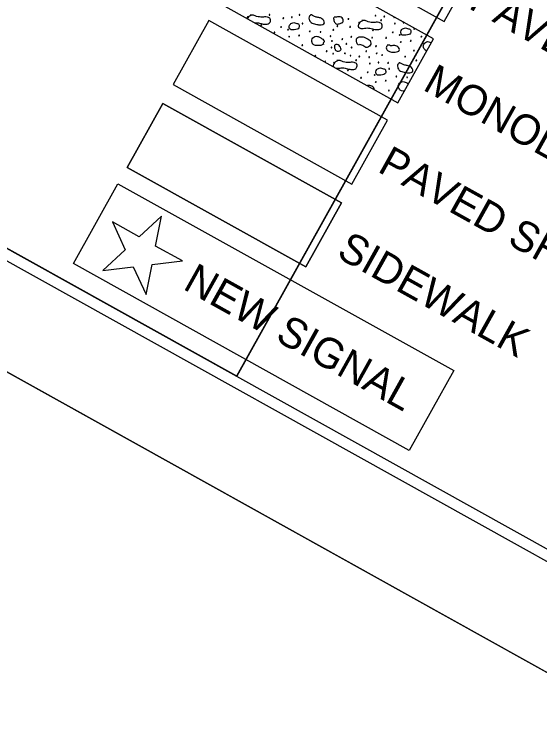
# Model space of a CAD drawing. Extents: x 1763454 to 1765483, y 710212 to 712009.
# Drawn here: x 1764801.1 to 1764922.7, y 710212.4 to 710377.6 of the extents above; entities that cross this region are included whole.
import ezdxf

# ---------------------------------------------------------------- set-up
doc = ezdxf.new("R2010")
doc.units = 0
for name, color, linetype in [('Default', 7, 'Continuous'), ('Matchline', 7, 'Continuous'), ('Old_Level_40', 7, 'Continuous'), ('Prop DSN Text', 7, 'Continuous'), ('Prop Grid Mask', 7, 'Continuous'), ('Prop RDY Traffic Signal CELL', 7, 'Continuous'), ('Prop Shade Light', 7, 'Continuous'), ('Prop Shade Medium', 7, 'Continuous'), ('Sheet Border Standard 30in CELL', 7, 'Continuous'), ('Sheet Cutting Line CELL', 7, 'Continuous'), ('Sheet Layout Plan Border', 7, 'Continuous'), ('Sheet Plot Border Inside CELL', 7, 'Continuous'), ('Sheet Plot Border Outside CELL', 7, 'Continuous')]:
    doc.layers.add(name, color=color, linetype=linetype)

msp = doc.modelspace()

# ---------------------------------------------------------------- linework, layer by layer
at = {"layer": 'Default'}
msp.add_lwpolyline([(1763634.19, 710972.32), (1763634.19, 710972.32), (1763806.94, 711282.53), (1764422.61, 711735.08), (1765280.77, 711257.19), (1765145.7, 711014.65), (1765228.38, 710968.6), (1764852.61, 710293.81)], close=True, dxfattribs=at)
at = {"layer": 'Matchline'}
for points in [[(1764854.98, 710376.93), (1764854.96, 710376.88), (1764855.1, 710376.82), (1764855.22, 710376.94), (1764855.12, 710377.03), (1764855.05, 710376.98), (1764855.01, 710376.94), (1764855, 710376.92)], [(1764855.86, 710377.31), (1764855.46, 710377.17), (1764855.16, 710376.91), (1764854.98, 710376.6)], [(1764856.67, 710375.67), (1764856.84, 710375.67), (1764857.67, 710375.67), (1764858.45, 710375.36), (1764859.47, 710375.3), (1764859.82, 710375.39), (1764860.37, 710375.63), (1764860.52, 710376.67), (1764859.71, 710377.02), (1764858.97, 710377.06), (1764858.56, 710376.89), (1764857.85, 710377.01), (1764857.23, 710377.05), (1764856.46, 710377.5), (1764855.96, 710377.44), (1764855.71, 710377.39)], [(1764860.07, 710377.5), (1764860.05, 710377.45), (1764860.19, 710377.39), (1764860.3, 710377.51), (1764860.21, 710377.6), (1764860.13, 710377.55), (1764860.1, 710377.52), (1764860.08, 710377.49)], [(1764863.26, 710376.72), (1764863.25, 710376.68), (1764863.38, 710376.62), (1764863.49, 710376.74), (1764863.4, 710376.82), (1764863.33, 710376.77), (1764863.29, 710376.74), (1764863.28, 710376.72)], [(1764865.25, 710376.95), (1764865.23, 710376.9), (1764865.37, 710376.83), (1764865.48, 710376.96), (1764865.39, 710377.04), (1764865.32, 710377), (1764865.28, 710376.96), (1764865.27, 710376.94)], [(1764867.03, 710377.49), (1764867.02, 710377.44), (1764867.15, 710377.38), (1764867.26, 710377.5), (1764867.17, 710377.58), (1764867.1, 710377.54), (1764867.06, 710377.5), (1764867.05, 710377.48)], [(1764869.7, 710377.36), (1764869.47, 710377.29), (1764869.28, 710377.04), (1764869.32, 710376.46), (1764869.66, 710375.64), (1764870.91, 710375.27), (1764871.76, 710375.17), (1764872.54, 710375.24), (1764873.02, 710375.59), (1764872.73, 710376.23), (1764872.36, 710376.62), (1764871.6, 710376.93), (1764870.74, 710376.91), (1764870.17, 710377.45), (1764869.74, 710377.52), (1764869.65, 710377.53)], [(1764875.03, 710376.96), (1764875, 710376.49), (1764875.12, 710375.96), (1764875.54, 710375.26), (1764876.3, 710375.42), (1764877.07, 710375.69), (1764877.28, 710375.87), (1764877.22, 710376.33), (1764877.03, 710376.81), (1764876.51, 710377.06), (1764876.08, 710377.03), (1764875.69, 710376.99), (1764875.3, 710376.96), (1764875.12, 710376.95)], [(1764884.6, 710377.3), (1764884.58, 710377.25), (1764884.72, 710377.19), (1764884.83, 710377.31), (1764884.74, 710377.39), (1764884.67, 710377.34), (1764884.63, 710377.31), (1764884.62, 710377.29)], [(1764886.65, 710377.09), (1764886.62, 710377.05), (1764886.76, 710376.98), (1764886.88, 710377.1), (1764886.78, 710377.19), (1764886.71, 710377.14), (1764886.68, 710377.11), (1764886.66, 710377.09)], [(1764888.92, 710376.96), (1764888.9, 710376.91), (1764889.04, 710376.85), (1764889.13, 710376.96), (1764889.13, 710376.98)], [(1764889.03, 710377.04), (1764889.02, 710377.03), (1764888.99, 710377), (1764888.96, 710376.97), (1764888.94, 710376.95)], [(1764858.19, 710375.16), (1764858.17, 710375.11), (1764858.31, 710375.04), (1764858.43, 710375.16), (1764858.33, 710375.25), (1764858.26, 710375.2), (1764858.22, 710375.17), (1764858.21, 710375.15)], [(1764865.8, 710375.73), (1764865.45, 710375.65), (1764864.9, 710375.4), (1764864.67, 710374.79), (1764864.81, 710374.27), (1764865.05, 710374), (1764865.92, 710374.02), (1764866.6, 710374.11), (1764867.09, 710374.46), (1764867.04, 710374.88), (1764867.02, 710375.31), (1764866.7, 710375.49), (1764866.29, 710375.53), (1764865.93, 710375.67), (1764865.8, 710375.73)], [(1764867.72, 710375.49), (1764867.7, 710375.44), (1764867.84, 710375.38), (1764867.95, 710375.5), (1764867.85, 710375.59), (1764867.78, 710375.54), (1764867.75, 710375.5), (1764867.73, 710375.48)], [(1764878.33, 710376.54), (1764878.31, 710376.49), (1764878.45, 710376.42), (1764878.56, 710376.55), (1764878.46, 710376.63), (1764878.39, 710376.59), (1764878.36, 710376.55), (1764878.34, 710376.53)], [(1764881.69, 710376.07), (1764881.27, 710375.92), (1764880.95, 710375.63), (1764880.7, 710375.13), (1764880.69, 710374.91), (1764880.89, 710374.39), (1764881.73, 710374.31), (1764883.18, 710374.56), (1764884.28, 710374.12), (1764885.3, 710374.06), (1764885.66, 710374.15), (1764886.21, 710374.39), (1764886.35, 710375.43), (1764885.54, 710375.78), (1764884.8, 710375.82), (1764884.4, 710375.65), (1764883.68, 710375.76), (1764883.06, 710375.81), (1764882.3, 710376.25), (1764881.79, 710376.2), (1764881.54, 710376.15)], [(1764880.81, 710375.69), (1764880.8, 710375.64), (1764880.93, 710375.58), (1764881.05, 710375.7), (1764880.95, 710375.78), (1764880.88, 710375.73), (1764880.85, 710375.7), (1764880.83, 710375.68)], [(1764885.9, 710376.26), (1764885.88, 710376.21), (1764886.02, 710376.15), (1764886.14, 710376.27), (1764886.04, 710376.35), (1764885.97, 710376.31), (1764885.93, 710376.27), (1764885.92, 710376.25)], [(1764889.1, 710375.48), (1764889.08, 710375.43), (1764889.22, 710375.37), (1764889.33, 710375.49), (1764889.23, 710375.57), (1764889.16, 710375.53), (1764889.13, 710375.49), (1764889.11, 710375.47)], [(1764891.08, 710375.7), (1764891.06, 710375.66), (1764891.21, 710375.59), (1764891.32, 710375.71), (1764891.22, 710375.8), (1764891.15, 710375.75), (1764891.12, 710375.72), (1764891.1, 710375.7)], [(1764861.22, 710373.42), (1764861.19, 710373.37), (1764861.34, 710373.31), (1764861.45, 710373.43), (1764861.35, 710373.52), (1764861.28, 710373.47), (1764861.24, 710373.43), (1764861.23, 710373.41)], [(1764862.76, 710374.7), (1764862.74, 710374.65), (1764862.87, 710374.59), (1764862.99, 710374.71), (1764862.89, 710374.79), (1764862.82, 710374.74), (1764862.79, 710374.71), (1764862.77, 710374.69)], [(1764864.36, 710374.05), (1764864.34, 710374), (1764864.48, 710373.94), (1764864.59, 710374.06), (1764864.49, 710374.15), (1764864.42, 710374.1), (1764864.39, 710374.06), (1764864.37, 710374.04)], [(1764869.38, 710373.69), (1764869.37, 710373.64), (1764869.5, 710373.58), (1764869.62, 710373.7), (1764869.52, 710373.78), (1764869.45, 710373.74), (1764869.41, 710373.7), (1764869.4, 710373.68)], [(1764871.88, 710373.53), (1764871.86, 710373.48), (1764872, 710373.41), (1764872.11, 710373.54), (1764872.01, 710373.62), (1764871.94, 710373.58), (1764871.91, 710373.54), (1764871.89, 710373.52)], [(1764874.84, 710374.02), (1764874.82, 710373.97), (1764874.96, 710373.91), (1764875.08, 710374.03), (1764874.97, 710374.12), (1764874.91, 710374.07), (1764874.87, 710374.04), (1764874.86, 710374.01)], [(1764875.78, 710374.88), (1764875.76, 710374.83), (1764875.9, 710374.77), (1764876.01, 710374.89), (1764875.91, 710374.98), (1764875.84, 710374.93), (1764875.81, 710374.89), (1764875.79, 710374.87)], [(1764878.72, 710374.72), (1764878.7, 710374.68), (1764878.84, 710374.61), (1764878.95, 710374.73), (1764878.85, 710374.82), (1764878.79, 710374.77), (1764878.75, 710374.74), (1764878.73, 710374.72)], [(1764884.03, 710373.91), (1764884.01, 710373.86), (1764884.14, 710373.8), (1764884.26, 710373.92), (1764884.16, 710374.01), (1764884.09, 710373.96), (1764884.06, 710373.93), (1764884.04, 710373.9)], [(1764888.59, 710373.45), (1764888.57, 710373.41), (1764888.71, 710373.34), (1764888.83, 710373.46), (1764888.73, 710373.55), (1764888.66, 710373.5), (1764888.62, 710373.47), (1764888.61, 710373.45)], [(1764891.63, 710374.49), (1764891.29, 710374.4), (1764890.73, 710374.16), (1764890.5, 710373.54), (1764890.65, 710373.02), (1764890.88, 710372.76), (1764891.76, 710372.78), (1764892.44, 710372.87), (1764892.93, 710373.21), (1764892.87, 710373.63), (1764892.85, 710374.06), (1764892.54, 710374.25), (1764892.13, 710374.29), (1764891.76, 710374.43), (1764891.63, 710374.49)], [(1764893.55, 710374.25), (1764893.53, 710374.2), (1764893.67, 710374.13), (1764893.79, 710374.26), (1764893.69, 710374.34), (1764893.62, 710374.3), (1764893.58, 710374.26), (1764893.57, 710374.24)], [(1764864.62, 710372.46), (1764864.6, 710372.41), (1764864.74, 710372.35), (1764864.85, 710372.47), (1764864.75, 710372.55), (1764864.68, 710372.51), (1764864.65, 710372.47), (1764864.63, 710372.45)], [(1764866.92, 710372.72), (1764866.9, 710372.68), (1764867.03, 710372.61), (1764867.15, 710372.73), (1764867.05, 710372.82), (1764866.98, 710372.77), (1764866.95, 710372.74), (1764866.93, 710372.72)], [(1764872.76, 710370.69), (1764872.19, 710370.4), (1764871.53, 710370.33), (1764870.52, 710370.39), (1764870.04, 710370.85), (1764869.85, 710371.74), (1764870.21, 710372.16), (1764870.61, 710372.51), (1764871.31, 710372.56), (1764871.89, 710372.27), (1764872.57, 710371.81), (1764872.84, 710371.46), (1764872.88, 710371.17), (1764872.66, 710371.13), (1764872.63, 710370.94), (1764872.62, 710370.88), (1764872.63, 710370.81)], [(1764874.19, 710372.57), (1764874.17, 710372.52), (1764874.31, 710372.45), (1764874.42, 710372.58), (1764874.32, 710372.66), (1764874.25, 710372.62), (1764874.22, 710372.58), (1764874.2, 710372.56)], [(1764876.92, 710371.87), (1764876.9, 710371.83), (1764877.04, 710371.76), (1764877.16, 710371.89), (1764877.06, 710371.97), (1764876.99, 710371.92), (1764876.95, 710371.89), (1764876.94, 710371.87)], [(1764879.01, 710372.41), (1764878.99, 710372.36), (1764879.12, 710372.3), (1764879.24, 710372.42), (1764879.14, 710372.51), (1764879.07, 710372.46), (1764879.04, 710372.43), (1764879.02, 710372.4)], [(1764880.89, 710370.58), (1764880.65, 710370.36), (1764880.35, 710371.04), (1764880.28, 710371.71), (1764880.32, 710372.13), (1764880.91, 710372.39), (1764881.73, 710372.49), (1764882.4, 710372.18), (1764883.08, 710371.8), (1764883.47, 710371.68), (1764883.72, 710370.85), (1764883.49, 710370.47), (1764883.21, 710370), (1764882.37, 710369.87), (1764882.1, 710370.31), (1764881.47, 710370.51), (1764881.27, 710370.58), (1764881.06, 710370.64)], [(1764883.85, 710372.19), (1764883.83, 710372.15), (1764883.97, 710372.08), (1764884.08, 710372.21), (1764883.99, 710372.29), (1764883.91, 710372.24), (1764883.88, 710372.21), (1764883.86, 710372.19)], [(1764887.05, 710372.18), (1764887.03, 710372.13), (1764887.17, 710372.06), (1764887.28, 710372.19), (1764887.18, 710372.27), (1764887.11, 710372.22), (1764887.08, 710372.19), (1764887.06, 710372.17)], [(1764890.19, 710372.81), (1764890.17, 710372.76), (1764890.31, 710372.69), (1764890.42, 710372.82), (1764890.33, 710372.9), (1764890.26, 710372.86), (1764890.22, 710372.82), (1764890.21, 710372.8)], [(1764895.22, 710372.44), (1764895.2, 710372.4), (1764895.34, 710372.33), (1764895.45, 710372.46), (1764895.35, 710372.54), (1764895.28, 710372.49), (1764895.25, 710372.46), (1764895.23, 710372.44)], [(1764867.66, 710370.45), (1764867.64, 710370.4), (1764867.78, 710370.33), (1764867.9, 710370.46), (1764867.8, 710370.54), (1764867.73, 710370.5), (1764867.69, 710370.46), (1764867.68, 710370.44)], [(1764874.52, 710371.44), (1764874.5, 710371.39), (1764874.64, 710371.33), (1764874.75, 710371.45), (1764874.66, 710371.53), (1764874.59, 710371.49), (1764874.55, 710371.45), (1764874.53, 710371.43)], [(1764875.4, 710369.62), (1764875.29, 710369.31), (1764875.94, 710368.97), (1764876.43, 710369.09), (1764876.84, 710369.46), (1764876.62, 710369.99), (1764876.35, 710370.42), (1764875.83, 710370.71), (1764875.27, 710370.61), (1764875.15, 710370.25), (1764875.21, 710369.9), (1764875.24, 710369.79), (1764875.29, 710369.68)], [(1764877.86, 710370.77), (1764877.84, 710370.72), (1764877.97, 710370.66), (1764878.09, 710370.78), (1764877.99, 710370.86), (1764877.92, 710370.82), (1764877.89, 710370.78), (1764877.87, 710370.76)], [(1764884.72, 710370.26), (1764884.7, 710370.21), (1764884.84, 710370.14), (1764884.95, 710370.26), (1764884.86, 710370.35), (1764884.79, 710370.3), (1764884.75, 710370.27), (1764884.74, 710370.25)], [(1764887.33, 710370.34), (1764887.26, 710370.12), (1764887.13, 710369.95), (1764887.3, 710369.28), (1764887.88, 710368.95), (1764888.91, 710368.8), (1764889.57, 710368.89), (1764890.13, 710369.06), (1764890.33, 710369.44), (1764890.09, 710369.95), (1764889.66, 710370.26), (1764889.14, 710370.41), (1764888.65, 710370.42), (1764888.35, 710370.23), (1764888.06, 710370.47), (1764887.7, 710370.5), (1764887.55, 710370.51), (1764887.41, 710370.49)], [(1764890.45, 710371.22), (1764890.43, 710371.17), (1764890.57, 710371.1), (1764890.69, 710371.23), (1764890.59, 710371.31), (1764890.52, 710371.26), (1764890.48, 710371.23), (1764890.47, 710371.21)], [(1764892.75, 710371.48), (1764892.73, 710371.43), (1764892.87, 710371.37), (1764892.98, 710371.49), (1764892.89, 710371.57), (1764892.82, 710371.53), (1764892.78, 710371.49), (1764892.77, 710371.47)], [(1764896.6, 710369.16), (1764896.21, 710369.29), (1764895.85, 710369.7), (1764895.69, 710370.5), (1764896.04, 710370.92), (1764896.45, 710371.27), (1764897.1, 710371.32), (1764897.37, 710371.18), (1764897.64, 710371.04)], [(1764873.28, 710369.07), (1764873.26, 710369.02), (1764873.4, 710368.96), (1764873.52, 710369.08), (1764873.42, 710369.17), (1764873.35, 710369.12), (1764873.32, 710369.08), (1764873.3, 710369.06)], [(1764874.43, 710369.95), (1764874.4, 710369.9), (1764874.54, 710369.84), (1764874.66, 710369.96), (1764874.56, 710370.04), (1764874.49, 710370), (1764874.46, 710369.96), (1764874.44, 710369.94)], [(1764874.82, 710368.5), (1764874.8, 710368.45), (1764874.94, 710368.38), (1764875.05, 710368.51), (1764874.96, 710368.59), (1764874.89, 710368.55), (1764874.85, 710368.51), (1764874.83, 710368.49)], [(1764877.53, 710368.56), (1764877.51, 710368.52), (1764877.65, 710368.45), (1764877.76, 710368.57), (1764877.66, 710368.66), (1764877.59, 710368.61), (1764877.56, 710368.58), (1764877.54, 710368.56)], [(1764879.07, 710369.94), (1764879.05, 710369.9), (1764879.19, 710369.83), (1764879.31, 710369.95), (1764879.2, 710370.04), (1764879.14, 710369.99), (1764879.1, 710369.96), (1764879.09, 710369.94)], [(1764882.45, 710369.05), (1764882.42, 710369.01), (1764882.57, 710368.94), (1764882.68, 710369.06), (1764882.58, 710369.15), (1764882.51, 710369.1), (1764882.48, 710369.07), (1764882.46, 710369.05)], [(1764884.88, 710368.59), (1764884.85, 710368.54), (1764884.99, 710368.48), (1764885.11, 710368.6), (1764885.01, 710368.69), (1764884.94, 710368.64), (1764884.91, 710368.6), (1764884.89, 710368.58)], [(1764893.5, 710369.21), (1764893.47, 710369.16), (1764893.61, 710369.09), (1764893.73, 710369.22), (1764893.63, 710369.3), (1764893.56, 710369.25), (1764893.53, 710369.22), (1764893.51, 710369.2)], [(1764870.66, 710368), (1764870.64, 710367.96), (1764870.79, 710367.89), (1764870.9, 710368.01), (1764870.8, 710368.1), (1764870.73, 710368.05), (1764870.7, 710368.02), (1764870.68, 710368)], [(1764875.59, 710365.13), (1764875.63, 710365.13), (1764876.16, 710365.1), (1764877.39, 710365.3), (1764878.49, 710364.87), (1764879.51, 710364.8), (1764879.86, 710364.89), (1764880.41, 710365.13), (1764880.56, 710366.17), (1764879.75, 710366.53), (1764879.01, 710366.56), (1764878.6, 710366.39), (1764877.88, 710366.51), (1764877.27, 710366.55), (1764876.5, 710367), (1764876, 710366.95), (1764875.75, 710366.89)], [(1764878.81, 710368.04), (1764878.78, 710367.99), (1764878.92, 710367.93), (1764879.04, 710368.05), (1764878.94, 710368.14), (1764878.87, 710368.09), (1764878.84, 710368.05), (1764878.82, 710368.03)], [(1764880.11, 710367), (1764880.09, 710366.96), (1764880.22, 710366.89), (1764880.34, 710367.01), (1764880.24, 710367.1), (1764880.17, 710367.05), (1764880.14, 710367.02), (1764880.12, 710367)], [(1764880.85, 710367.84), (1764880.83, 710367.79), (1764880.97, 710367.72), (1764881.09, 710367.85), (1764880.99, 710367.94), (1764880.92, 710367.89), (1764880.88, 710367.85), (1764880.87, 710367.83)], [(1764883.13, 710367.7), (1764883.11, 710367.66), (1764883.25, 710367.59), (1764883.36, 710367.71), (1764883.26, 710367.8), (1764883.2, 710367.75), (1764883.16, 710367.72), (1764883.15, 710367.7)], [(1764886.12, 710368.19), (1764886.1, 710368.14), (1764886.24, 710368.08), (1764886.35, 710368.2), (1764886.26, 710368.29), (1764886.19, 710368.24), (1764886.15, 710368.2), (1764886.14, 710368.18)], [(1764891.44, 710367.82), (1764891.42, 710367.77), (1764891.56, 710367.7), (1764891.68, 710367.83), (1764891.58, 710367.91), (1764891.51, 710367.86), (1764891.47, 710367.83), (1764891.46, 710367.81)], [(1764894.05, 710366.94), (1764894.03, 710366.89), (1764894.17, 710366.82), (1764894.29, 710366.95), (1764894.19, 710367.03), (1764894.12, 710366.98), (1764894.08, 710366.95), (1764894.07, 710366.93)], [(1764872.98, 710366.66), (1764872.97, 710366.63), (1764873.02, 710366.61), (1764873.05, 710366.61)], [(1764873.13, 710366.75), (1764873.12, 710366.75), (1764873.08, 710366.75), (1764873.04, 710366.71), (1764873.01, 710366.68), (1764872.99, 710366.66)], [(1764875.9, 710366.81), (1764875.48, 710366.67), (1764875.16, 710366.37), (1764874.91, 710365.89), (1764874.9, 710365.69), (1764874.96, 710365.48)], [(1764875.02, 710366.43), (1764875, 710366.38), (1764875.14, 710366.32), (1764875.26, 710366.44), (1764875.15, 710366.53), (1764875.08, 710366.48), (1764875.05, 710366.44), (1764875.03, 710366.42)], [(1764883.3, 710366.23), (1764883.28, 710366.18), (1764883.42, 710366.12), (1764883.53, 710366.24), (1764883.44, 710366.32), (1764883.37, 710366.28), (1764883.33, 710366.24), (1764883.32, 710366.22)], [(1764885.84, 710365.24), (1764885.49, 710365.15), (1764884.93, 710364.9), (1764884.71, 710364.29), (1764884.85, 710363.77), (1764885.09, 710363.5), (1764885.96, 710363.52), (1764886.64, 710363.62), (1764887.13, 710363.96), (1764887.07, 710364.38), (1764887.05, 710364.81), (1764886.74, 710364.99), (1764886.33, 710365.03), (1764885.97, 710365.17), (1764885.84, 710365.24)], [(1764885.29, 710366.45), (1764885.27, 710366.4), (1764885.41, 710366.33), (1764885.52, 710366.46), (1764885.42, 710366.55), (1764885.36, 710366.5), (1764885.32, 710366.46), (1764885.31, 710366.44)], [(1764887.52, 710366.37), (1764887.5, 710366.32), (1764887.64, 710366.26), (1764887.75, 710366.38), (1764887.65, 710366.47), (1764887.58, 710366.42), (1764887.55, 710366.38), (1764887.53, 710366.36)], [(1764890.18, 710366.24), (1764889.95, 710366.18), (1764889.77, 710365.92), (1764889.8, 710365.34), (1764890.14, 710364.52), (1764891.4, 710364.15), (1764892.25, 710364.05), (1764893.02, 710364.12), (1764893.5, 710364.47), (1764893.21, 710365.11), (1764892.84, 710365.5), (1764892.09, 710365.81), (1764891.22, 710365.79), (1764890.66, 710366.33), (1764890.22, 710366.41), (1764890.13, 710366.41)], [(1764878.23, 710364.66), (1764878.21, 710364.61), (1764878.35, 710364.54), (1764878.47, 710364.67), (1764878.37, 710364.75), (1764878.3, 710364.7), (1764878.26, 710364.67), (1764878.24, 710364.65)], [(1764882.8, 710364.2), (1764882.78, 710364.15), (1764882.91, 710364.09), (1764883.03, 710364.21), (1764882.93, 710364.29), (1764882.86, 710364.25), (1764882.83, 710364.21), (1764882.81, 710364.19)], [(1764884.4, 710363.55), (1764884.38, 710363.5), (1764884.52, 710363.44), (1764884.63, 710363.56), (1764884.53, 710363.65), (1764884.46, 710363.6), (1764884.43, 710363.57), (1764884.41, 710363.55)], [(1764887.76, 710364.99), (1764887.74, 710364.94), (1764887.88, 710364.88), (1764887.99, 710365), (1764887.89, 710365.09), (1764887.82, 710365.04), (1764887.79, 710365.01), (1764887.77, 710364.99)], [(1764881.25, 710362.92), (1764881.23, 710362.87), (1764881.38, 710362.81), (1764881.49, 710362.93), (1764881.39, 710363.02), (1764881.32, 710362.97), (1764881.28, 710362.94), (1764881.27, 710362.92)], [(1764884.66, 710361.96), (1764884.63, 710361.91), (1764884.77, 710361.85), (1764884.89, 710361.97), (1764884.79, 710362.05), (1764884.72, 710362.01), (1764884.69, 710361.97), (1764884.67, 710361.95)], [(1764886.96, 710362.23), (1764886.94, 710362.18), (1764887.07, 710362.12), (1764887.19, 710362.23), (1764887.09, 710362.32), (1764887.02, 710362.27), (1764886.99, 710362.24), (1764886.97, 710362.22)], [(1764889.42, 710363.19), (1764889.41, 710363.14), (1764889.54, 710363.08), (1764889.65, 710363.2), (1764889.56, 710363.28), (1764889.49, 710363.24), (1764889.45, 710363.2), (1764889.44, 710363.18)], [(1764891.42, 710359.86), (1764891.28, 710359.85), (1764890.7, 710359.76), (1764890.08, 710360.35), (1764889.89, 710361.24), (1764890.25, 710361.66), (1764890.65, 710362.01), (1764891.35, 710362.06), (1764891.78, 710361.84), (1764892.2, 710361.58), (1764892.33, 710361.49)], [(1764891.92, 710363.03), (1764891.9, 710362.98), (1764892.04, 710362.91), (1764892.15, 710363.04), (1764892.05, 710363.13), (1764891.98, 710363.08), (1764891.95, 710363.04), (1764891.93, 710363.02)], [(1764884.43, 710360.2), (1764884.45, 710360.3), (1764884.35, 710360.65), (1764883.86, 710361.01), (1764883.34, 710361.15), (1764882.92, 710361.16), (1764882.87, 710361.13), (1764882.82, 710361.1)], [(1764887.7, 710359.95), (1764887.68, 710359.9), (1764887.82, 710359.84), (1764887.94, 710359.96), (1764887.84, 710360.05), (1764887.77, 710360), (1764887.73, 710359.96), (1764887.72, 710359.94)]]:
    msp.add_open_spline(points, degree=3, dxfattribs=at)
at = {"layer": 'Old_Level_40'}
for points in [[(1764908.83, 710390.79), (1764867.48, 710413.81), (1764859.24, 710399.01), (1764900.58, 710375.98)], [(1764898.16, 710371.95), (1764856.81, 710394.98), (1764848.57, 710380.18), (1764889.91, 710357.15)], [(1764887.48, 710353.12), (1764846.14, 710376.15), (1764837.9, 710361.35), (1764879.24, 710338.32)], [(1764876.81, 710333.96), (1764835.47, 710356.99), (1764827.23, 710342.18), (1764868.57, 710319.16)]]:
    msp.add_lwpolyline(points, close=True, dxfattribs=at)
at = {"layer": 'Prop Grid Mask'}
msp.add_lwpolyline([(1764825.11, 710338.39), (1764902.82, 710295.12), (1764892.53, 710276.64), (1764814.82, 710319.91)], close=True, dxfattribs=at)
at = {"layer": 'Prop RDY Traffic Signal CELL'}
msp.add_lwpolyline([(1764830, 710326.09), (1764823.82, 710329.53), (1764826.8, 710323.11), (1764821.61, 710318.29), (1764828.65, 710319.14), (1764831.63, 710312.71), (1764832.99, 710319.66), (1764840.02, 710320.51), (1764833.83, 710323.95), (1764835.19, 710330.91), (1764830, 710326.09)], dxfattribs=at)
at = {"layer": 'Prop Shade Light'}
msp.add_lwpolyline([(1764835.47, 710356.99), (1764876.81, 710333.96), (1764868.57, 710319.16), (1764827.23, 710342.18)], close=True, dxfattribs=at)
at = {"layer": 'Prop Shade Medium'}
msp.add_lwpolyline([(1764887.48, 710353.12), (1764846.14, 710376.15), (1764837.9, 710361.35), (1764879.24, 710338.32), (1764887.48, 710353.12)], dxfattribs=at)
at = {"layer": 'Sheet Border Standard 30in CELL'}
msp.add_lwpolyline([(1765455.55, 711159.88), (1764145.05, 711889.67), (1763634.19, 710972.32), (1764944.69, 710242.53)], close=True, dxfattribs=at)
at = {"layer": 'Sheet Cutting Line CELL'}
msp.add_line((1763476.13, 711031.72), (1764947.38, 710212.42), dxfattribs=at)
at = {"layer": 'Sheet Layout Plan Border'}
msp.add_line((1765203.86, 710924.73), (1764852.55, 710293.84), dxfattribs=at)
msp.add_lwpolyline([(1764852.55, 710293.84), (1764570.56, 710450.87), (1764630.41, 710563.94), (1764222.54, 710791), (1764159.35, 710679.87), (1763634.19, 710972.32)], dxfattribs=at)
at = {"layer": 'Sheet Plot Border Inside CELL'}
msp.add_lwpolyline([(1765467.71, 711156.02), (1764011.74, 711966.82), (1763498.41, 711045.01), (1764954.37, 710234.22)], close=True, dxfattribs=at)
at = {"layer": 'Sheet Plot Border Outside CELL'}
msp.add_lwpolyline([(1765482.56, 711173.45), (1764011.31, 711992.76), (1763476.13, 711031.72), (1764947.38, 710212.42)], close=True, dxfattribs=at)

# ---------------------------------------------------------------- texts
at = {"layer": 'Prop DSN Text'}
for s, p in [('PAVEMENT REMOVAL', (1764906, 710379.13)), ('MONOLITHIC ISLAND', (1764895.4, 710360.26)), ('PAVED SHOULDER', (1764884.94, 710341.31)), ('SIDEWALK', (1764875.42, 710321.51)), ('NEW SIGNAL', (1764839.89, 710314.13))]:
    msp.add_text(s, height=7, rotation=330.8875, dxfattribs=at).set_placement(p)

doc.saveas('drawing.dxf')
